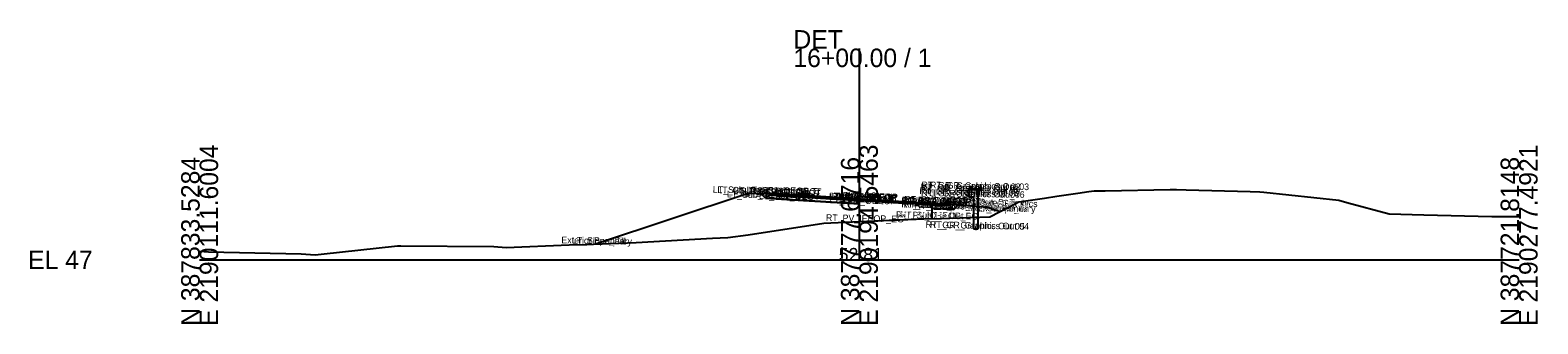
# Model space of a CAD drawing. Extents: x -26 to 1203, y -10 to 9543.
# Drawn here: x -25.7 to 202.8, y 5990.3 to 6034.8 of the extents above; entities that cross this region are included whole.
import ezdxf

# ---------------------------------------------------------------- set-up
doc = ezdxf.new("R2010")
doc.units = 0
for name, color, linetype in [('Default', 7, 'Continuous'), ('Exist CMT Pavement', 7, 'Continuous'), ('Exist Cross Section Cell', 7, 'Continuous'), ('Exist XS Center Line Elevation Label', 7, 'Continuous'), ('Exist XS Ground Line', 7, 'Continuous'), ('Prop CMT Guardrail Graphics', 7, 'Continuous'), ('Prop CMT Pvmt Course 1', 7, 'Continuous'), ('Prop CMT Pvmt Course 1 Wedge', 7, 'Continuous'), ('Prop CMT Pvmt Course 2', 7, 'Continuous'), ('Prop CMT Pvmt Course 2 Wedge', 7, 'Continuous'), ('Prop CMT Pvmt Course 3', 7, 'Continuous'), ('Prop CMT Pvmt Course 3 Wedge', 7, 'Continuous'), ('Prop CMT Pvmt Surface', 7, 'Continuous'), ('Prop CMT Pvmt Surface Shoulder', 7, 'Continuous'), ('Prop CMT Pvmt Wedge Surface 1', 7, 'Continuous'), ('Prop CMT Pvmt Wedge Surface 2', 7, 'Continuous'), ('Prop CMT Pvmt Wedge Surface 3', 7, 'Continuous'), ('Prop CMT Shld Paved Course 1', 7, 'Continuous'), ('Prop CMT Shld Paved Course 2', 7, 'Continuous'), ('Prop CMT Shld Paved Course 3', 7, 'Continuous'), ('Prop CMT Slope Grass', 7, 'Continuous'), ('Prop CMT Subgrade Earthwork', 7, 'Continuous'), ('Scratch_Level_0', 7, 'Continuous')]:
    doc.layers.add(name, color=color, linetype=linetype)

msp = doc.modelspace()

# ---------------------------------------------------------------- linework, layer by layer
at = {"layer": 'Exist CMT Pavement'}
msp.add_lwpolyline([(100, 6005.81), (111, 6006.25)], dxfattribs=at)
at = {"layer": 'Exist Cross Section Cell'}
for p, q in [((100, 6000), (100, 6032.02)), ((0, 6000), (100, 6000)), ((100, 6000), (200, 6000))]:
    msp.add_line(p, q, dxfattribs=at)
at = {"layer": 'Exist XS Ground Line'}
for p, q in [((134.8, 6010.34), (135.58, 6010.45)), ((135.58, 6010.45), (137.25, 6010.45)), ((137.25, 6010.45), (147.09, 6010.65)), ((147.09, 6010.65), (148.08, 6010.67)), ((148.08, 6010.67), (149.51, 6010.63)), ((149.51, 6010.63), (159.25, 6010.35)), ((121.25, 6007.28), (124.19, 6008.79)), ((124.19, 6008.79), (128.07, 6009.36)), ((128.07, 6009.36), (129.92, 6009.65)), ((129.92, 6009.65), (133.11, 6010.1)), ((133.11, 6010.1), (134.8, 6010.34)), ((159.25, 6010.35), (160.71, 6010.32)), ((160.71, 6010.32), (161.31, 6010.26)), ((161.31, 6010.26), (172.67, 6009.03)), ((172.67, 6009.03), (173.91, 6008.68)), ((173.91, 6008.68), (180.31, 6006.97)), ((100, 6005.81), (108.94, 6006.2)), ((108.94, 6006.2), (112.46, 6006.28)), ((112.46, 6006.28), (113.7, 6006.32)), ((113.7, 6006.32), (119.75, 6006.52)), ((119.75, 6006.52), (121.25, 6007.28)), ((180.31, 6006.97), (185.57, 6006.82)), ((185.57, 6006.82), (195.88, 6006.56)), ((195.88, 6006.56), (200, 6006.58)), ((80.07, 6003.41), (83.15, 6003.8)), ((83.15, 6003.8), (94.61, 6005.57)), ((94.61, 6005.57), (100, 6005.81)), ((0, 6001.31), (1.32, 6001.24)), ((18.41, 6000.89), (29.99, 6002.11)), ((29.99, 6002.11), (30.51, 6002.13)), ((30.51, 6002.13), (44.57, 6002.02)), ((44.57, 6002.02), (46.44, 6001.89)), ((46.44, 6001.89), (56.02, 6002.28)), ((56.02, 6002.28), (58.5, 6002.32)), ((58.5, 6002.32), (59.7, 6002.4)), ((59.7, 6002.4), (66.19, 6002.64)), ((66.19, 6002.64), (77.75, 6003.27)), ((77.75, 6003.27), (80.07, 6003.41)), ((1.32, 6001.24), (15.41, 6000.91)), ((15.41, 6000.91), (17.49, 6000.79)), ((17.49, 6000.79), (18.41, 6000.89))]:
    msp.add_line(p, q, dxfattribs=at)
at = {"layer": 'Prop CMT Guardrail Graphics'}
for points in [[(117.98, 6010.72), (116.64, 6010.72), (116.37, 6010.43)], [(116.37, 6010.43), (116.64, 6010.13)], [(117.98, 6004.72), (117.98, 6010.72)], [(116.64, 6010.13), (116.37, 6009.84)], [(116.37, 6009.84), (116.64, 6009.55), (117.31, 6009.55)], [(117.31, 6009.55), (117.31, 6004.72)], [(117.31, 6004.72), (117.98, 6004.72)]]:
    msp.add_lwpolyline(points, dxfattribs=at)
at = {"layer": 'Prop CMT Pvmt Course 1'}
for points in [[(100, 6009.26), (89, 6009.92)], [(89, 6009.92), (89, 6009.67)], [(89, 6009.67), (100, 6009.01)], [(100, 6009.01), (100, 6009.26)], [(100, 6009.26), (111, 6008.61)], [(100, 6009.01), (100, 6009.26)], [(111, 6008.48), (100, 6009.14)], [(100, 6009.14), (100, 6009.01), (100, 6009.01)], [(111, 6008.61), (111, 6008.36), (111, 6008.36), (111, 6008.48)]]:
    msp.add_lwpolyline(points, dxfattribs=at)
msp.add_lwpolyline([(100, 6009.01), (100, 6009.14), (100, 6009.14), (100, 6009.01)], close=True, dxfattribs=at)
at = {"layer": 'Prop CMT Pvmt Course 1 Wedge'}
msp.add_lwpolyline([(100, 6009.14), (111, 6008.48)], dxfattribs=at)
at = {"layer": 'Prop CMT Pvmt Course 2'}
for points in [[(89, 6009.67), (100, 6009.01)], [(100, 6009.01), (89, 6009.67)], [(89, 6009.67), (89, 6009.67)], [(100, 6009.01), (100, 6009.01)], [(111, 6008.36), (111, 6008.36)]]:
    msp.add_lwpolyline(points, dxfattribs=at)
msp.add_lwpolyline([(111, 6008.36), (111, 6008.36), (111, 6008.36)], close=True, dxfattribs=at)
at = {"layer": 'Prop CMT Pvmt Course 2 Wedge'}
msp.add_lwpolyline([(100, 6009.01), (111, 6008.36)], dxfattribs=at)
at = {"layer": 'Prop CMT Pvmt Course 3'}
for points in [[(100, 6009.01), (89, 6009.67)], [(89, 6009.67), (89, 6009.17)], [(89, 6009.17), (100, 6008.51)], [(100, 6008.51), (100, 6009.01)], [(111, 6008.36), (111, 6008.36), (111, 6007.86), (111, 6007.86)], [(111, 6007.86), (111, 6008.36)]]:
    msp.add_lwpolyline(points, dxfattribs=at)
at = {"layer": 'Prop CMT Pvmt Course 3 Wedge'}
msp.add_lwpolyline([(100, 6009.01), (111, 6008.36)], dxfattribs=at)
at = {"layer": 'Prop CMT Pvmt Surface'}
for points in [[(100, 6009.26), (89, 6009.92)], [(100, 6009.26), (111, 6008.61)]]:
    msp.add_lwpolyline(points, dxfattribs=at)
at = {"layer": 'Prop CMT Pvmt Surface Shoulder'}
for points in [[(89, 6009.92), (87, 6010.04)], [(111, 6008.61), (113, 6008.49)]]:
    msp.add_lwpolyline(points, dxfattribs=at)
at = {"layer": 'Prop CMT Pvmt Wedge Surface 1'}
for points in [[(100, 6009.14), (111, 6008.48)], [(111, 6008.36), (111, 6008.61)], [(111, 6008.48), (111, 6008.36), (111, 6008.36)]]:
    msp.add_lwpolyline(points, dxfattribs=at)
at = {"layer": 'Prop CMT Pvmt Wedge Surface 2'}
for points in [[(100, 6009.01), (111, 6008.36)], [(111, 6008.36), (111, 6008.61)]]:
    msp.add_lwpolyline(points, dxfattribs=at)
at = {"layer": 'Prop CMT Pvmt Wedge Surface 3'}
for points in [[(100, 6009.01), (111, 6008.36)], [(111, 6008.36), (111, 6008.61)]]:
    msp.add_lwpolyline(points, dxfattribs=at)
at = {"layer": 'Prop CMT Shld Paved Course 1'}
for points in [[(89, 6009.92), (87, 6010.04), (86.76, 6009.8)], [(86.76, 6009.8), (89, 6009.67)], [(89, 6009.67), (89, 6009.92)], [(111, 6008.61), (113, 6008.49), (113.27, 6008.22)], [(111, 6008.36), (111, 6008.61)], [(113.27, 6008.22), (111, 6008.36)]]:
    msp.add_lwpolyline(points, dxfattribs=at)
at = {"layer": 'Prop CMT Shld Paved Course 2'}
for points in [[(89, 6009.67), (86.76, 6009.8)], [(86.76, 6009.8), (86.76, 6009.8)], [(86.76, 6009.8), (89, 6009.67)], [(89, 6009.67), (89, 6009.67)], [(111, 6008.36), (113.27, 6008.22)], [(113.27, 6008.22), (111, 6008.36)], [(111, 6008.36), (111, 6008.36)], [(113.27, 6008.22), (113.27, 6008.22)]]:
    msp.add_lwpolyline(points, dxfattribs=at)
at = {"layer": 'Prop CMT Shld Paved Course 3'}
for points in [[(89, 6009.67), (86.76, 6009.8), (86.26, 6009.83), (85.79, 6009.36)], [(85.79, 6009.36), (89, 6009.17)], [(89, 6009.17), (89, 6009.67)], [(111, 6008.36), (113.27, 6008.22), (113.77, 6008.19), (114.3, 6007.66)], [(111, 6007.86), (111, 6008.36)], [(114.3, 6007.66), (111, 6007.86)]]:
    msp.add_lwpolyline(points, dxfattribs=at)
at = {"layer": 'Prop CMT Slope Grass'}
for points in [[(87, 6010.04), (83, 6010.03), (60.16, 6002.42)], [(113, 6008.49), (116.37, 6008.22)], [(116.37, 6008.22), (119.37, 6007.98)], [(119.37, 6007.98), (121.33, 6007.32)]]:
    msp.add_lwpolyline(points, dxfattribs=at)
at = {"layer": 'Prop CMT Subgrade Earthwork'}
for points in [[(85.79, 6009.36), (85.11, 6010.03)], [(89, 6009.17), (85.79, 6009.36)], [(100, 6008.51), (89, 6009.17)], [(114.3, 6007.66), (114.97, 6008.33)], [(111, 6007.86), (111, 6007.86)], [(111, 6007.86), (111, 6006.25)], [(111, 6007.86), (114.3, 6007.66)]]:
    msp.add_lwpolyline(points, dxfattribs=at)

# ---------------------------------------------------------------- texts
at = {"layer": 'Default'}
msp.add_text('-', height=0.0001, dxfattribs=at).set_placement((0, 6000))
at = {"layer": 'Exist Cross Section Cell'}
for s, p in [('DET', (90, 6032.02)), ('16+00.00 / 1', (90, 6029.22)), ('EL 47', (-26, 5998.6))]:
    msp.add_text(s, height=2.8, dxfattribs=at).set_placement(p)
for s, p in [('E 2190111.6004', (2.8, 5990)), ('E 2190194.5463', (102.8, 5990)), ('E 2190277.4921', (202.8, 5990)), ('N 387833.5284', (0, 5990)), ('N 387777.6716', (100, 5990)), ('N 387721.8148', (200, 5990))]:
    msp.add_text(s, height=2.8, rotation=90, dxfattribs=at).set_placement(p)
at = {"layer": 'Exist XS Center Line Elevation Label'}
msp.add_text('52.81', height=2, dxfattribs=at).set_placement((96.87, 5999.81))
at = {"layer": 'Scratch_Level_0'}
for s, p in [('LT_Sub_Trench_Out_DLT', (77.77, 6010.18)), ('LT_GS_OS_CTL', (78.46, 6010.12)), ('LT_Sub_Trench_Out', (79.9, 6009.47)), ('LT_PS3_Shelf_Out', (80.92, 6009.93)), ('LT_PS3_OEOP', (82.55, 6009.88)), ('LT_PS2_OEOP', (82.55, 6009.88)), ('LT_PS1_OEOP', (82.91, 6010.12)), ('LT_PV2_OEOT', (84.75, 6009.75)), ('LT_PV3_OEOT', (84.75, 6009.75)), ('LT_PV1_OEOT', (84.87, 6010)), ('RT_GR_Graphics Out 08', (109.09, 6009.98)), ('RT_GR_Graphics Out 01', (109.26, 6010.56)), ('RT_GR_Graphics Out 07', (109.34, 6009.69)), ('RT_GR_Graphics Out 09', (109.36, 6010.28)), ('RT_GR_Graphics Out 02', (109.39, 6010.86)), ('RT_GR_Graphics Out 06', (110.03, 6009.69)), ('RT_GR_Graphics Out 03', (110.7, 6010.86)), ('LT_Sub_OEOT', (84.77, 6009.25)), ('LT_PV2_OEEOP', (95.39, 6009.1)), ('LT_PV3_OEEOP', (95.39, 6009.1)), ('LT_Sub_OEEOP', (95.42, 6008.6)), ('LT_PV1_OEEOP', (95.51, 6009.22)), ('RT_PV2_IEEOP', (95.71, 6009.09)), ('RT_PV3_IEEOP', (95.71, 6009.09)), ('LT_PV2_IEEOP', (95.77, 6009.09)), ('RT_PV1_IEEOP', (95.83, 6009.22)), ('LT_PV1_IEEOP', (95.89, 6009.22)), ('PV2_PGL', (97.35, 6009.06)), ('PV1_PGL', (97.47, 6009.31)), ('RT_PV2_OEEOP', (106.33, 6008.45)), ('RT_PV3_OEEOP', (106.33, 6008.45)), ('RT_Sub_OEEOP', (106.36, 6007.95)), ('RT_PV1_OEEOP', (106.45, 6008.57)), ('RT_PV3_OEOT', (106.69, 6008.44)), ('RT_PV2_OEOT', (106.69, 6008.44)), ('RT_Sub_OEOT', (106.71, 6007.94)), ('RT_PV1_OEOT', (106.81, 6008.69)), ('RT_GS_OS_GR_Face_Graphics', (107.31, 6008.39)), ('RT_Sub_Trench_Out_DLT', (107.56, 6008.47)), ('RT_Sub_Trench_Out', (108.35, 6007.78)), ('RT_PS3_Shelf_Out', (108.36, 6008.3)), ('RT_PS1_OEOP', (108.85, 6008.57)), ('RT_PS3_OEOP', (108.99, 6008.3)), ('RT_PS2_OEOP', (108.99, 6008.3)), ('RT_GS_OS_CTL', (114.78, 6008.07)), ('Exterior Boundary', (115.99, 6007.43)), ('RT_Slope_Fill', (117.51, 6007.4)), ('RT_PV_IEEOP_EG', (94.92, 6005.91)), ('RT_PV_OEEOP_EG', (105.54, 6006.35)), ('RT_Sub Tie Out', (106.1, 6006.34)), ('RT_GR_Graphics Out 05', (110.03, 6004.86)), ('RT_GR_Graphics Out 04', (110.69, 6004.86)), ('Exterior Boundary', (54.82, 6002.52)), ('LT_Slope_Fill', (56.4, 6002.49))]:
    msp.add_text(s, height=1, rotation=358.8836, dxfattribs=at).set_placement(p)

doc.saveas('drawing.dxf')
